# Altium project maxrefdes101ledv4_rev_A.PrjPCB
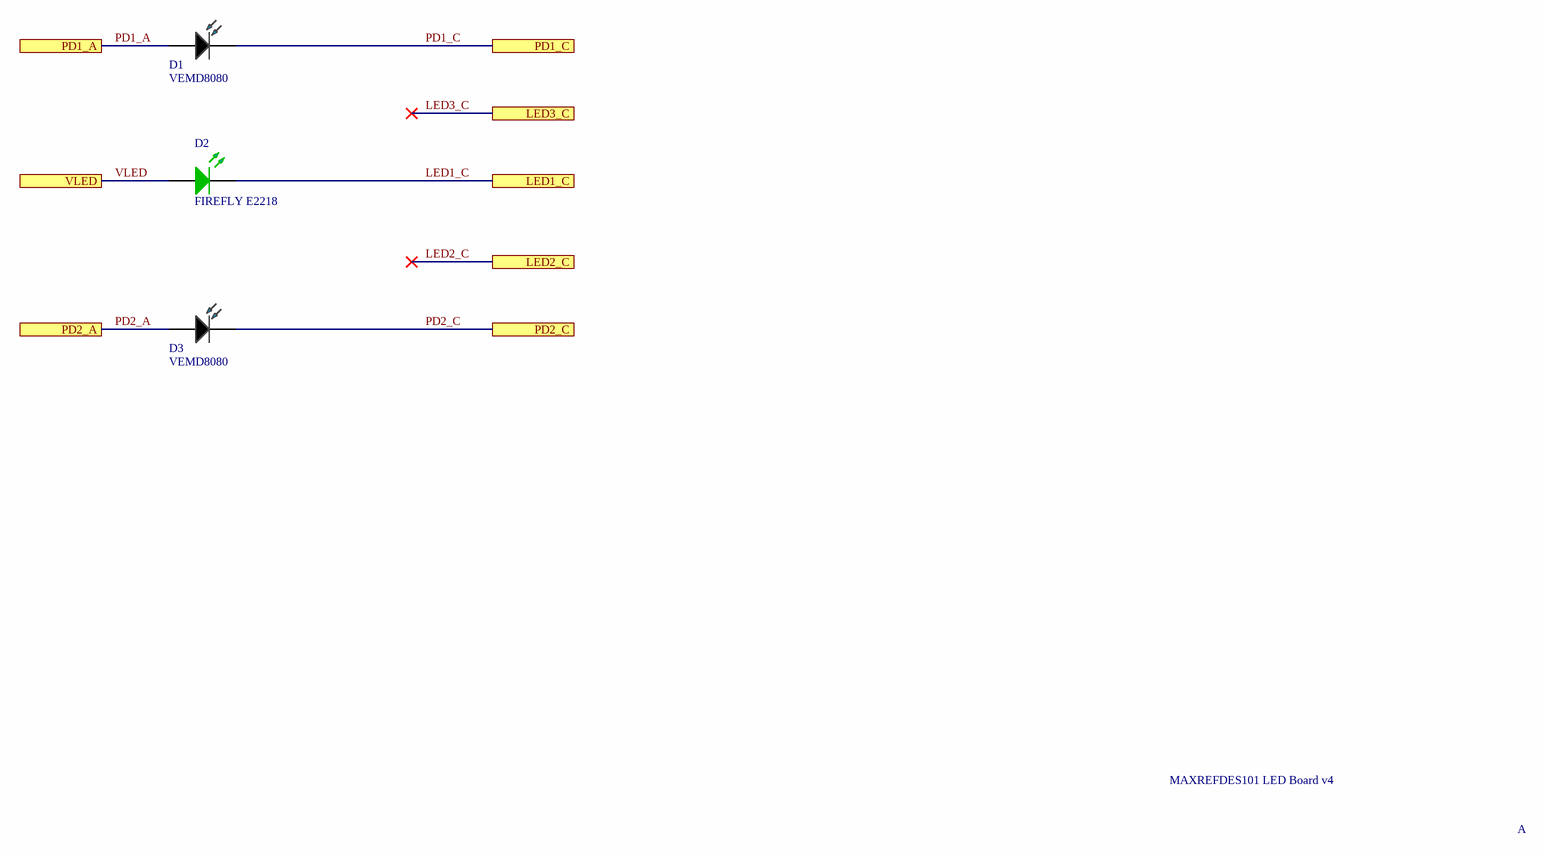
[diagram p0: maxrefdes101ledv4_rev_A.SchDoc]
1 sheet, 3 parts. Net scope: flat (ports and power ports of the same name join across sheets).
Board file: maxrefdes101ledv4_rev_A.PcbDoc

## Sheet maxrefdes101ledv4_rev_A.SchDoc
size C

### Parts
D1  VEMD8080  [PHOTODIODE_VEMD8080]
D2  FIREFLY E2218  [LED_FIREFLY_E2218]
D3  VEMD8080  [PHOTODIODE_VEMD8080]

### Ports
LED1_C, LED2_C, LED3_C, PD1_A, PD1_C, PD2_A, PD2_C, VLED

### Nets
LED1_C: D2.1 ; port LED1_C
PD1_A: D1.2 ; port PD1_A
PD1_C: D1.1 ; port PD1_C
PD2_A: D3.2 ; port PD2_A
PD2_C: D3.1 ; port PD2_C
VLED: D2.2 ; port VLED

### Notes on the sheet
- MAXREFDES101 LED Board v4
- A

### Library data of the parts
D1 D3 = PHOTODIODE_VEMD8080: Silicon PIN Photodiode; Manufacturer: Vishay
D2 = LED_FIREFLYE2218: OSRAM WHRM SMD LED Vf+2.3V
